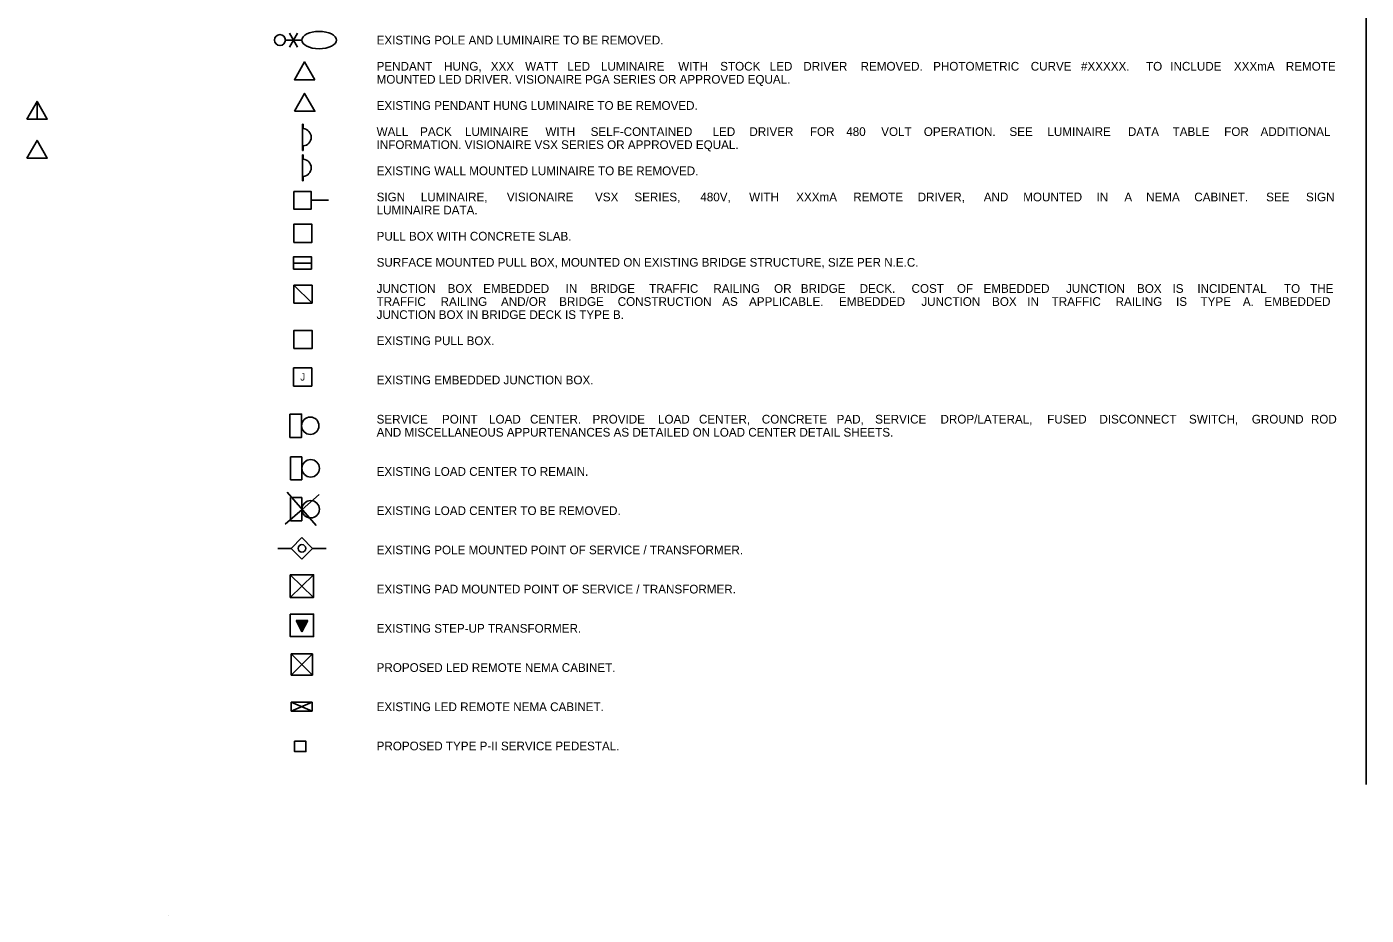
# Model space of a CAD drawing. Extents: x -1500 to -654, y -278 to 331.
# Drawn here: x -1500.3 to -1039.2, y -278.3 to 27.5 of the extents above; entities that cross this region are included whole.
import ezdxf

# ---------------------------------------------------------------- set-up
doc = ezdxf.new("R2010")
doc.units = 0
for name, color, linetype in [('AdhocPoint_dp', 7, 'Continuous'), ('ControllerP', 7, 'Continuous'), ('Default', 7, 'Continuous'), ('ElecMisc_ep', 7, 'Continuous'), ('JunctBoxA', 7, 'Continuous'), ('LoadCenter', 7, 'Continuous'), ('Logo_dp', 7, 'Continuous'), ('Miscellaneous3', 7, 'Continuous'), ('SheetBorder_dp', 7, 'Continuous'), ('SheetLines_dp', 7, 'Continuous'), ('SignPanel', 7, 'Continuous')]:
    doc.layers.add(name, color=color, linetype=linetype)

# ---------------------------------------------------------------- blocks, each defined once
blk = doc.blocks.new('EPoleLumRmv')
at = {"layer": 'Logo_dp'}
for p, q in [((-0.00352, -0.0088), (0.00352, -0.00474)), ((0.00352, -0.0088), (-0.00352, -0.00474)), ((0, -0.00271), (0, -0.01083))]:
    blk.add_line(p, q, dxfattribs=at)
blk.add_circle((0, 0), 0.00271, dxfattribs=at)
blk.add_ellipse((0, -0.01949), major_axis=(0, -0.00866), ratio=0.5, dxfattribs=at)

msp = doc.modelspace()

# ---------------------------------------------------------------- linework, layer by layer
at = {"layer": 'AdhocPoint_dp'}
for p, q in [((-1405.09, -6.02), (-1405.39, -6.02)), ((-1405.39, -6.02), (-1405.39, -15.02)), ((-1405.09, -7.54), (-1405.09, -6.02)), ((-1405.09, -15.02), (-1405.09, -13.51)), ((-1405.39, -15.02), (-1405.09, -15.02)), ((-1405.39, -25.52), (-1405.39, -16.52)), ((-1405.39, -16.52), (-1405.09, -16.52)), ((-1405.09, -16.52), (-1405.09, -18.04)), ((-1405.09, -25.52), (-1405.39, -25.52)), ((-1405.09, -24.01), (-1405.09, -25.52))]:
    msp.add_line(p, q, dxfattribs=at)
for points in [[(-1401.1, 9.31), (-1408.17, 9.31), (-1404.64, 15.43)], [(-1500.3, -4.28), (-1493.23, -4.28), (-1496.76, 1.84)], [(-1496.76, 1.84), (-1493.23, -4.28), (-1496.76, -4.28)], [(-1408.17, -1.53), (-1401.1, -1.53), (-1404.64, 4.59)], [(-1500.3, -17.69), (-1493.23, -17.69), (-1496.76, -11.57)]]:
    msp.add_lwpolyline(points, close=True, dxfattribs=at)
for centre in [(-1405.39, -10.52), (-1405.39, -21.02)]:
    msp.add_arc(centre, 3, 275.7392, 84.2608, dxfattribs=at)
at = {"layer": 'ControllerP'}
for p, q in [((-1409.27, -188.4), (-1401.98, -195.64)), ((-1409.27, -195.64), (-1401.98, -188.4)), ((-1409.3, -205.02), (-1402.08, -208.03)), ((-1402.08, -205.02), (-1409.3, -208.03)), ((-1409.3, -205.02), (-1402.08, -205.02)), ((-1409.3, -208.03), (-1409.3, -205.02)), ((-1402.08, -205.02), (-1402.08, -208.03)), ((-1402.08, -208.03), (-1409.3, -208.03))]:
    msp.add_line(p, q, dxfattribs=at)
for points in [[(-1409.27, -188.4), (-1401.98, -188.4), (-1401.98, -195.64), (-1409.27, -195.64)], [(-1408.08, -218.44), (-1404.18, -218.44), (-1404.18, -222.02), (-1408.08, -222.02)]]:
    msp.add_lwpolyline(points, close=True, dxfattribs=at)
at = {"layer": 'Default'}
msp.add_circle((-1405.56, -152.03), 1.3, dxfattribs=at)
at = {"layer": 'ElecMisc_ep'}
for p, q in [((-1409.57, -168.9), (-1401.56, -161.14)), ((-1409.57, -161.14), (-1401.56, -168.91)), ((-1405.56, -180.82), (-1407.56, -176.82)), ((-1407.56, -176.82), (-1403.56, -176.82)), ((-1407.36, -176.82), (-1405.56, -180.82)), ((-1405.56, -180.82), (-1407.16, -176.82)), ((-1405.56, -180.82), (-1406.96, -176.82)), ((-1405.56, -180.82), (-1406.76, -176.82)), ((-1405.56, -180.82), (-1406.56, -176.82)), ((-1405.56, -180.82), (-1406.36, -176.82)), ((-1405.56, -180.82), (-1406.16, -176.82)), ((-1405.56, -180.82), (-1405.96, -176.82)), ((-1405.56, -180.82), (-1405.76, -176.82)), ((-1405.56, -180.82), (-1405.36, -176.82)), ((-1405.56, -180.82), (-1405.16, -176.82)), ((-1405.56, -180.82), (-1404.96, -176.82)), ((-1405.56, -180.82), (-1404.76, -176.82)), ((-1405.56, -180.82), (-1404.36, -176.82)), ((-1405.56, -180.82), (-1404.16, -176.82)), ((-1405.56, -180.82), (-1403.96, -176.82)), ((-1405.56, -180.82), (-1403.77, -176.82)), ((-1403.56, -176.82), (-1405.56, -180.82)), ((-1405.56, -180.82), (-1405.56, -176.82)), ((-1405.56, -180.82), (-1404.56, -176.82))]:
    msp.add_line(p, q, dxfattribs=at)
for points in [[(-1409.57, -161.14), (-1401.56, -161.14), (-1401.56, -168.91), (-1409.57, -168.9)], [(-1409.57, -174.64), (-1401.56, -174.64), (-1401.56, -182.41), (-1409.57, -182.4)]]:
    msp.add_lwpolyline(points, close=True, dxfattribs=at)
at = {"layer": 'JunctBoxA'}
for p, q in [((-1408.51, -55.88), (-1408.51, -51.71)), ((-1408.51, -51.71), (-1402.26, -51.71)), ((-1402.26, -53.8), (-1408.51, -53.8)), ((-1402.26, -51.71), (-1402.26, -55.88)), ((-1402.26, -55.88), (-1408.51, -55.88))]:
    msp.add_line(p, q, dxfattribs=at)
msp.add_lwpolyline([(-1402.26, -53.8), (-1408.51, -53.8), (-1408.51, -51.71), (-1402.26, -51.71)], close=True, dxfattribs=at)
at = {"layer": 'LoadCenter'}
for p, q in [((-1402.39, -32.21), (-1396.39, -32.21)), ((-1409.7, -105.83), (-1405.7, -105.83)), ((-1409.7, -113.83), (-1409.7, -105.83)), ((-1405.7, -105.83), (-1405.7, -113.83)), ((-1405.7, -113.83), (-1409.7, -113.83)), ((-1409.56, -120.49), (-1405.56, -120.49)), ((-1409.56, -128.49), (-1409.56, -120.49)), ((-1405.56, -120.49), (-1405.56, -128.49)), ((-1405.56, -128.49), (-1409.56, -128.49)), ((-1410.7, -132.71), (-1400.68, -144.11)), ((-1405.51, -138.62), (-1399.69, -133.5)), ((-1409.56, -134.58), (-1405.56, -134.58)), ((-1409.56, -142.58), (-1409.56, -134.58)), ((-1405.56, -134.58), (-1405.56, -142.58)), ((-1411.32, -143.73), (-1405.51, -138.62)), ((-1405.56, -142.58), (-1409.56, -142.58)), ((-1409.24, -152.03), (-1413.88, -152.03)), ((-1409.24, -152.03), (-1405.56, -148.35)), ((-1405.56, -155.7), (-1409.24, -152.03)), ((-1405.56, -148.35), (-1401.89, -152.03)), ((-1401.89, -152.03), (-1405.56, -155.7)), ((-1397.24, -152.03), (-1401.89, -152.03))]:
    msp.add_line(p, q, dxfattribs=at)
for points in [[(-1408.39, -29.21), (-1402.39, -29.21), (-1402.39, -35.21), (-1408.39, -35.21)], [(-1409.7, -105.83), (-1405.7, -105.83), (-1405.7, -113.83), (-1409.7, -113.83)]]:
    msp.add_lwpolyline(points, close=True, dxfattribs=at)
for centre in [(-1402.7, -109.83), (-1402.7, -109.83), (-1402.56, -124.49), (-1402.56, -138.58)]:
    msp.add_circle(centre, 3, dxfattribs=at)
at = {"layer": 'Miscellaneous3'}
msp.add_line((-1039.17, 240.54), (-1039.17, -233.32), dxfattribs=at)
at = {"layer": 'SheetLines_dp'}
for p, q in [((-1408.35, -61.38), (-1402.1, -61.38)), ((-1408.35, -67.63), (-1408.35, -61.38)), ((-1408.35, -61.38), (-1402.1, -67.63)), ((-1402.1, -61.38), (-1402.1, -67.63)), ((-1402.1, -67.63), (-1408.35, -67.63)), ((-1408.42, -89.9), (-1402.17, -89.9)), ((-1408.42, -96.15), (-1408.42, -89.9)), ((-1402.17, -89.9), (-1402.17, -96.15)), ((-1402.17, -96.15), (-1408.42, -96.15))]:
    msp.add_line(p, q, dxfattribs=at)
for points in [[(-1408.39, -46.7), (-1402.14, -46.7), (-1402.14, -40.45), (-1408.39, -40.45)], [(-1408.35, -83.25), (-1402.1, -83.25), (-1402.1, -77), (-1408.35, -77)]]:
    msp.add_lwpolyline(points, close=True, dxfattribs=at)
at = {"layer": 'SignPanel'}
msp.add_line((-1451.67, -278.32), (-1451.67, -278.32), dxfattribs=at)

# ---------------------------------------------------------------- block references
at = {"layer": 'Logo_dp', "xscale": 690.9505022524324, "yscale": 690.9505022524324, "rotation": 89.99999999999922}
msp.add_blockref('EPoleLumRmv', (-1413.13, 22.94), dxfattribs=at)

# ---------------------------------------------------------------- texts
at = {"layer": 'SheetBorder_dp'}
for s, p in [('EXISTING POLE AND LUMINAIRE TO BE REMOVED.', (-1379.86, 21.43)), ('PENDANT ', (-1379.86, 12.43)), ('HUNG, ', (-1356.63, 12.43)), ('XXX ', (-1340.56, 12.43)), ('WATT ', (-1328.72, 12.43)), ('LED ', (-1314.18, 12.43)), ('LUMINAIRE ', (-1302.62, 12.43)), ('WITH ', (-1276.03, 12.43)), ('STOCK ', (-1261.57, 12.43)), ('LED ', (-1244.52, 12.43)), ('DRIVER ', (-1232.96, 12.43)), ('REMOVED. ', (-1213.24, 12.43)), ('PHOTOMETRIC ', (-1188.27, 12.43)), ('CURVE ', (-1154.66, 12.43)), ('#XXXXX. ', (-1137.37, 12.43)), ('TO ', (-1114.98, 12.43)), ('INCLUDE ', (-1106.61, 12.43)), ('XXXmA ', (-1084.73, 12.43)), ('REMOTE ', (-1066.85, 12.43)), ('MOUNTED LED DRIVER. VISIONAIRE PGA SERIES OR APPROVED EQUAL.', (-1379.86, 7.93)), ('EXISTING PENDANT HUNG LUMINAIRE TO BE REMOVED.', (-1379.86, -1.07)), ('WALL ', (-1379.86, -10.07)), ('PACK ', (-1364.89, -10.07)), ('LUMINAIRE ', (-1349.45, -10.07)), ('WITH ', (-1321.75, -10.07)), ('SELF-CONTAINED ', (-1306.17, -10.07)), ('LED ', (-1264.21, -10.07)), ('DRIVER ', (-1251.53, -10.07)), ('FOR ', (-1230.69, -10.07)), ('480 ', (-1218.18, -10.07)), ('VOLT ', (-1206.14, -10.07)), ('OPERATION. ', (-1191.48, -10.07)), ('SEE ', (-1162.01, -10.07)), ('LUMINAIRE ', (-1148.92, -10.07)), ('DATA ', (-1121.21, -10.07)), ('TABLE ', (-1105.82, -10.07)), ('FOR ', (-1088.06, -10.07)), ('ADDITIONAL ', (-1075.55, -10.07)), ('INFORMATION. VISIONAIRE VSX SERIES OR APPROVED EQUAL.', (-1379.86, -14.57)), ('EXISTING WALL MOUNTED LUMINAIRE TO BE REMOVED.', (-1379.86, -23.57)), ('SIGN ', (-1379.86, -32.57)), ('LUMINAIRE, ', (-1364.64, -32.57)), ('VISIONAIRE ', (-1335.02, -32.57)), ('VSX ', (-1304.67, -32.57)), ('SERIES, ', (-1291.12, -32.57)), ('480V, ', (-1268.42, -32.57)), ('WITH ', (-1251.61, -32.57)), ('XXXmA ', (-1235.4, -32.57)), ('REMOTE ', (-1215.76, -32.57)), ('DRIVER, ', (-1193.59, -32.57)), ('AND ', (-1170.84, -32.57)), ('MOUNTED ', (-1157.25, -32.57)), ('IN ', (-1132.03, -32.57)), ('A ', (-1122.43, -32.57)), ('NEMA ', (-1114.94, -32.57)), ('CABINET. ', (-1098.36, -32.57)), ('SEE ', (-1073.62, -32.57)), ('SIGN ', (-1059.9, -32.57)), ('LUMINAIRE DATA.', (-1379.86, -37.07)), ('PULL BOX WITH CONCRETE SLAB. ', (-1379.86, -46.07)), ('SURFACE MOUNTED PULL BOX, MOUNTED ON EXISTING BRIDGE STRUCTURE, SIZE PER N.E.C.', (-1379.86, -55.07)), ('JUNCTION ', (-1379.86, -64.07)), ('BOX ', (-1355.41, -64.07)), ('EMBEDDED ', (-1343.19, -64.07)), ('IN ', (-1314.78, -64.07)), ('BRIDGE ', (-1306.3, -64.07)), ('TRAFFIC ', (-1286.04, -64.07)), ('RAILING ', (-1263.93, -64.07)), ('OR ', (-1243.03, -64.07)), ('BRIDGE ', (-1233.82, -64.07)), ('DECK. ', (-1213.56, -64.07)), (' COST ', (-1196.82, -64.07)), ('OF ', (-1180.08, -64.07)), ('EMBEDDED ', (-1170.93, -64.07)), ('JUNCTION ', (-1142.52, -64.07)), ('BOX ', (-1118.08, -64.07)), ('IS ', (-1105.85, -64.07)), ('INCIDENTAL ', (-1097.31, -64.07)), ('TO ', (-1067.49, -64.07)), ('THE ', (-1058.49, -64.07)), ('TRAFFIC ', (-1379.86, -68.57)), ('RAILING ', (-1357.84, -68.57)), ('AND/OR ', (-1337.04, -68.57)), ('BRIDGE ', (-1317.02, -68.57)), ('CONSTRUCTION ', (-1296.86, -68.57)), ('AS ', (-1260.87, -68.57)), ('APPLICABLE. ', (-1251.65, -68.57)), ('EMBEDDED ', (-1220.65, -68.57)), ('JUNCTION ', (-1192.33, -68.57)), ('BOX ', (-1167.98, -68.57)), ('IN ', (-1155.84, -68.57)), ('TRAFFIC ', (-1147.47, -68.57)), ('RAILING ', (-1125.44, -68.57)), ('IS ', (-1104.64, -68.57)), ('TYPE ', (-1096.2, -68.57)), ('A. ', (-1081.63, -68.57)), ('EMBEDDED ', (-1074.21, -68.57)), ('JUNCTION BOX IN BRIDGE DECK IS TYPE B.', (-1379.86, -73.07)), ('EXISTING PULL BOX.', (-1379.86, -82.07)), ('EXISTING EMBEDDED JUNCTION BOX.', (-1379.86, -95.57)), ('SERVICE ', (-1379.86, -109.07)), ('POINT ', (-1357.36, -109.07)), ('LOAD ', (-1341.15, -109.07)), ('CENTER. ', (-1327.05, -109.07)), ('PROVIDE ', (-1305.54, -109.07)), ('LOAD ', (-1282.98, -109.07)), ('CENTER, ', (-1268.88, -109.07)), ('CONCRETE ', (-1247.25, -109.07)), ('SERVICE ', (-1208.23, -109.07)), ('DROP/LATERAL, ', (-1185.73, -109.07)), ('FUSED ', (-1149, -109.07)), ('DISCONNECT ', (-1131.02, -109.07)), ('SWITCH, ', (-1100.18, -109.07)), ('GROUND ', (-1078.56, -109.07)), ('ROD ', (-1058.22, -109.07)), ('AND MISCELLANEOUS APPURTENANCES AS DETAILED ON LOAD CENTER DETAIL SHEETS.  ', (-1379.86, -113.57)), ('PAD, ', (-1221.5, -109.07)), ('EXISTING LOAD CENTER TO REMAIN.', (-1379.86, -127.07)), ('EXISTING LOAD CENTER TO BE REMOVED.', (-1379.86, -140.57)), ('EXISTING POLE MOUNTED POINT OF SERVICE / TRANSFORMER.', (-1379.86, -154.07)), ('EXISTING PAD MOUNTED POINT OF SERVICE / TRANSFORMER.', (-1379.86, -167.57)), ('EXISTING STEP-UP TRANSFORMER.', (-1379.86, -181.07)), ('PROPOSED LED REMOTE NEMA CABINET.', (-1379.86, -194.57)), ('EXISTING LED REMOTE NEMA CABINET.', (-1379.86, -208.07)), ('PROPOSED TYPE P-II SERVICE PEDESTAL.', (-1379.86, -221.57))]:
    msp.add_text(s, height=3, dxfattribs=at).set_placement(p)
at = {"layer": 'SheetLines_dp'}
msp.add_text('J', height=2.5, dxfattribs=at).set_placement((-1406.14, -94.27))

doc.saveas('drawing.dxf')
